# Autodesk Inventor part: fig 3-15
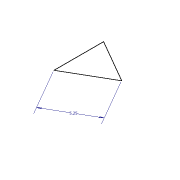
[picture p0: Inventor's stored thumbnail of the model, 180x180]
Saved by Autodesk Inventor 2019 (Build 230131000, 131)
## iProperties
Created: 2009-11
Part Number: fig 3-15
Document SubType Name: Modeling
Designer: Sham
Density: 1 g/cm^3
Material: Generic
Appearance: Default
Author: Sham
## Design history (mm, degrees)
sketch "Sketch1"
  geometry: L1 (0.077, -0.115)-(0.077, -5.365); L2 (0.077, -5.365)-(4.624, -2.74); L3 (4.624, -2.74)-(0.077, -0.115)
  constraints: 6 end point, 2 equal length, 1 vertical
  dimensions: "d1" = 5.25 dimension on L1.start L1.end L1 L2.end L2 L3; "d1" = 5.25 distance of L1.end L2.end
